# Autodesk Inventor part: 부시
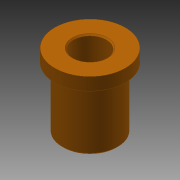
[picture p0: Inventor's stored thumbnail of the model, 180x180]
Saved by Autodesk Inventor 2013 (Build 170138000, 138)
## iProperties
Company: 한국ATC센터
Created: 2015-11
Part Number: 부시
Document SubType Name: Modeling
Designer: mdu
Density: 7.86 g/cm^3
Material: 강철, 연강
Mass: 65.5031 g
Surface Area: 42.0516 cm^2
Volume: 8.33373 cm^3
Author: mdu
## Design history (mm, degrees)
sketch "스케치1"
  geometry: C1 r 11 at (0, 0) reference; C2 r 14 at (0, 0) reference; C3 r 11 at (0, 0) reference; 1 further point
  node "참조1"
  node "참조2"
extrude "돌출1" new body sketch "스케치1" distance "d0" = 5; taper "d1" = 0 deg
extrude "돌출2" join sketch "스케치1" distance "d2" = 24; taper "d3" = 0 deg
hole "구멍1" diameter "d6" = 13; stored, may be unused: countersink angle "d10" = 90 deg, drill point angle "d12" = 118 deg; dims "d4" = 10, "d5" = 10, "d7" = 6, "d8" = 4, "d9" = 2, "d11" = 8
chamfer "모따기1" distance "d13" = 0.5; stored, may be unused: second distance "d14" = 2, angle "d15" = 45 deg
chamfer "모따기2" distance "d16" = 0.5; stored, may be unused: second distance "d17" = 2, angle "d18" = 45 deg
node "솔리드1"
